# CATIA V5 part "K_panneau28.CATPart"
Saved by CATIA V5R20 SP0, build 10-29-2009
Part number: panneau 28
Publications: "demi largeur balancier", "epaisseur pieces", "rayon congé", "Plan.00", "liaison 24/28", "liaison 21/28", "liaison 28/29 sur 28", "liaison 28/38 sur 28"
Bounding box of the stored display mesh (mm): x -30 to 75, y 120.03 to 369.976, z -84.996 to 475
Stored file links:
  G:\Khaled_CFAO_2011\SIL\SIL_GR2\mdardier\Khaled\CAD_ThinkMOTION\K_panneau28.CATPart
  G:\Khaled_CFAO_2011\SIL\SIL_GR2\mdardier\Khaled\CAD_ThinkMOTION\K_ass_tandem.CATProduct
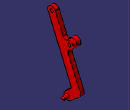
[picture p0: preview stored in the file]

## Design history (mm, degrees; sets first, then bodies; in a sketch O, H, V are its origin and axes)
External parameters (linked from other documents)
  `External.demi largeur balancier` = 50 mm
  `External.epaisseur pieces` = 30 mm
  `External.rayon congé` = 20 mm
Set1
  Plane1 "Plan.00": linked copy from another document
  Point1 "liaison 24/28": linked copy from another document
  Point2 "liaison 21/28": linked copy from another document
  Point3 "liaison 28/29 sur 28": linked copy from another document
  Point4 "liaison 28/38 sur 28": linked copy from another document
Set2
  Boundary1: Boundary face of Pad1 from Sketch1.A8
  Boundary2: Boundary face of Pad1 from Sketch1.A8
  Extract1: ExtractElem edge of Boundary2
  Boundary3: Boundary face of Pad1 from Sketch1.A7
  Extract2: ExtractElem edge of Boundary3
Body1 (main body)
  Sketch1 on Plane1, origin (0, 0, 0), H (0, 1, 0), V (0, 0, 1)
    construction line L1 (150, 445) -> (340, 0)
    point P1 (150, 445)
    point P2 (340, 0)
    line L2 (177.5904, 456.7802) -> (244.4071, 300.2883)
    line L3 (303.7111, 8.5926) -> (122.4096, 433.2198)
    arc A1 centre (340, 0) radius 30 from (367.5904, 11.7802) to (359.3783, -22.9016) cw
    arc A2 centre (150, 445) radius 30 from (122.4096, 433.2198) to (177.5904, 456.7802) cw
    reference projected point E1 (340, 0) from Point1
    reference projected point E2 (150, 445) from Point2
    arc A3 centre (285, 285) radius 30 from (296.7802, 257.4096) to (273.2198, 312.5904) ccw
    point P6 (285, 285)
    reference projected point E3 (285, 285) from Point3
    arc A4 centre (275, -55) radius 30 from (255.6217, -32.0984) to (294.3783, -77.9016) ccw
    point P7 (275, -55)
    reference projected point E4 (275, -55) from Point4
    circle A5 centre (150, 445) radius 12.5
    point P8 (150, 445)
    reference projected point E5 (150, 445) from Point2
    circle A6 centre (285, 285) radius 12.5
    point P9 (285, 285)
    reference projected point E6 (285, 285) from Point3
    circle A7 centre (340, 0) radius 20
    point P10 (340, 0)
    reference projected point E7 (340, 0) from Point1
    circle A8 centre (275, -55) radius 12.5
    point P11 (275, -55)
    reference projected point E8 (275, -55) from Point4
    line L4 (255.6217, -32.0984) -> (303.7111, 8.5926)
    line L5 (294.3783, -77.9016) -> (359.3783, -22.9016)
    line L6 (273.2198, 312.5904) -> (244.4071, 300.2883)
    line L7 (296.7802, 257.4096) -> (267.9674, 245.1076)
    point P19 (267.9674, 245.1076)
    line L8 (267.9674, 245.1076) -> (367.5904, 11.7802)
    distance L1 L2 = 30 {= `External.demi largeur balancier` /2+`External.demi largeur balancier` /10}
    radius A3 = 30 {= `External.demi largeur balancier` /2+`External.demi largeur balancier` /10}
    radius A4 = 30 {= `External.demi largeur balancier` /2+`External.demi largeur balancier` /10}
    radius A5 = 12.5 {= `External.demi largeur balancier` /4}
    radius A6 = 12.5 {= `External.demi largeur balancier` /4}
    radius A7 = 20 {= `External.demi largeur balancier` *2/5}
    radius A8 = 12.5 {= `External.demi largeur balancier` /4}
    tangency: A1 L2, A2 L2, A1 L3, A2 L3, L4 A1, L5 A1, L6 A3, L7 A3, L4 A4, A4 L5
    coincidence: P2 E1, P1 E2, P6 E3, P7 E4, P8 E5, P9 E6, P10 E7, P11 E8, P19 L2, L2 L8
    perpendicularity: L6 L2, L2 L7
  Pad1: profile Sketch1, direction (1, 0, 0), length 30 {= `External.epaisseur pieces`}
  Fillet1: radius 20 {= `External.rayon congé`}, on edge [face of Pad1 from Sketch1.L2 | face of Pad1 from Sketch1.L6]; edge [face of Pad1 from Sketch1.L7 | face of Pad1 from Sketch1.L8]; edge [face of Pad1 from Sketch1.L4 | face of Pad1 from Sketch1.L3]
  Sketch2 on start face of Pad1, origin (0, 0, 0), H (0, -1, 0), V (0, 0, 1)
    circle A1 centre (-285, 285) radius 12.5
    point P1 (-285, 285)
    reference projected point E1 (-285, 285) from Point3
    circle A2 centre (-285, 285) radius 30
    point P2 (-285, 285)
    reference projected point E2 (-285, 285) from Point3
    radius A1 = 12.5 {= `External.demi largeur balancier` /4}
    radius A2 = 30 {= `External.demi largeur balancier` /2+`External.demi largeur balancier` /10}
    coincidence: P1 E1, P2 E2
  Pad2: profile Sketch2, direction (-1, 0, 0), length 30 {= `External.epaisseur pieces`}
  Pad3: profile Extract1, length 45
  Fillet2: radius 10, on end face of Pad3
  Pad4: profile Extract2, up to end face of Pad1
